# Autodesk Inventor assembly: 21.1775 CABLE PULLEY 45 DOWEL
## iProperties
Created: 2007-05
Part Number: 21.1775 CABLE PULLEY 45 DOWEL
Document SubType Name: Assembly
Designer: Andy Moles
Author: Andy Moles
